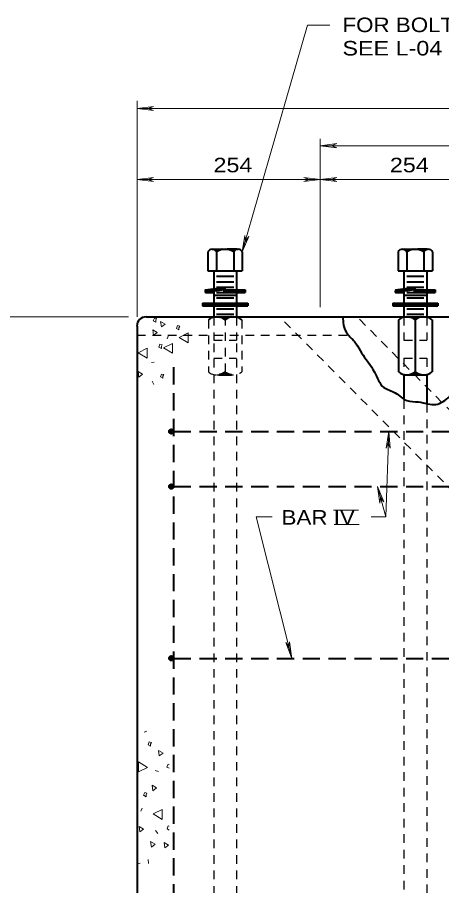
# Model space of a CAD drawing. Extents: x 312583 to 312854, y 144419 to 144597.
# Drawn here: x 312620 to 312642.19, y 144464.5 to 144509.86 of the extents above; entities that cross this region are included whole.
import ezdxf

# ---------------------------------------------------------------- set-up
doc = ezdxf.new("R2010")
doc.units = 0
doc.header["$LTSCALE"] = 0.3
doc.linetypes.add('MEDIUM_DASHED', pattern=[4.5, 3, -1.5])
doc.linetypes.add('SHORT_DASHED', pattern=[2.7, 1.5, -1.2])
doc.layers.add('1', color=7, linetype='Continuous', lineweight=25)
doc.layers.add('2', color=7, linetype='Continuous', lineweight=13)

msp = doc.modelspace()

# ---------------------------------------------------------------- linework, layer by layer
at = {"layer": '1', "lineweight": 40}
for p, q in [((312630.1901, 144497.7458), (312631.5395, 144497.7458)), ((312640.1338, 144497.7458), (312641.4831, 144497.7458)), ((312629.9678, 144497.6001), (312629.9678, 144496.6111)), ((312630.4201, 144497.6001), (312630.4201, 144496.6111)), ((312631.3171, 144497.6001), (312631.3171, 144496.6111)), ((312631.7618, 144497.6001), (312631.7618, 144496.6111)), ((312639.9115, 144497.6001), (312639.9115, 144496.6111)), ((312640.3638, 144497.6001), (312640.3638, 144496.6111)), ((312641.2608, 144497.6001), (312641.2608, 144496.6111)), ((312641.7055, 144497.6001), (312641.7055, 144496.6111)), ((312629.9678, 144496.6111), (312631.7618, 144496.6111)), ((312630.2668, 144496.6111), (312630.2668, 144494.2114)), ((312631.4628, 144496.6111), (312631.4628, 144494.2114)), ((312639.9115, 144496.6111), (312641.7055, 144496.6111)), ((312640.2105, 144496.6111), (312640.2105, 144494.2114)), ((312641.4065, 144496.6111), (312641.4065, 144494.2114)), ((312630.4201, 144496.3274), (312631.3171, 144496.3274)), ((312630.4201, 144496.0438), (312631.3171, 144496.0438)), ((312640.3638, 144496.3274), (312641.2608, 144496.3274)), ((312640.3638, 144496.0438), (312641.2608, 144496.0438)), ((312629.8298, 144495.6221), (312629.8298, 144495.4841)), ((312630.4201, 144495.7678), (312631.3171, 144495.7678)), ((312630.4201, 144495.4841), (312631.3171, 144495.4841)), ((312630.7805, 144495.4841), (312631.9075, 144495.4841)), ((312630.8188, 144495.6221), (312631.9075, 144495.6221)), ((312631.9075, 144495.6221), (312631.9075, 144495.4841)), ((312639.7735, 144495.6221), (312639.7735, 144495.4841)), ((312640.3638, 144495.7678), (312641.2608, 144495.7678)), ((312640.3638, 144495.4841), (312641.2608, 144495.4841)), ((312640.7241, 144495.4841), (312641.8511, 144495.4841)), ((312640.7625, 144495.6221), (312641.8511, 144495.6221)), ((312641.8511, 144495.6221), (312641.8511, 144495.4841)), ((312630.2668, 144495.3384), (312631.4628, 144495.3384)), ((312630.4201, 144495.2004), (312631.3171, 144495.2004)), ((312640.2105, 144495.3384), (312641.4065, 144495.3384)), ((312640.3638, 144495.2004), (312641.2608, 144495.2004)), ((312629.6841, 144494.9168), (312632.0455, 144494.9168)), ((312629.6841, 144494.9168), (312629.6841, 144494.7788)), ((312629.6841, 144494.8784), (312632.0455, 144494.8784)), ((312629.6841, 144494.8401), (312632.0455, 144494.8401)), ((312629.6841, 144494.8094), (312632.0455, 144494.8094)), ((312629.6841, 144494.7788), (312632.0455, 144494.7788)), ((312630.4201, 144494.6331), (312631.3171, 144494.6331)), ((312632.0455, 144494.9168), (312632.0455, 144494.7788)), ((312639.6278, 144494.9168), (312641.9891, 144494.9168)), ((312639.6278, 144494.9168), (312639.6278, 144494.7788)), ((312639.6278, 144494.8784), (312641.9891, 144494.8784)), ((312639.6278, 144494.8401), (312641.9891, 144494.8401)), ((312639.6278, 144494.8094), (312641.9891, 144494.8094)), ((312639.6278, 144494.7788), (312641.9891, 144494.7788)), ((312640.3638, 144494.6331), (312641.2608, 144494.6331)), ((312641.9891, 144494.9168), (312641.9891, 144494.7788)), ((312626.7325, 144494.2114), (312644.9408, 144494.2114)), ((312630.2668, 144494.2114), (312631.4628, 144494.2114)), ((312630.4201, 144494.3494), (312631.3171, 144494.3494)), ((312630.4278, 144494.2114), (312631.3018, 144494.2114)), ((312640.2105, 144494.2114), (312641.4065, 144494.2114)), ((312640.3638, 144494.3494), (312641.2608, 144494.3494)), ((312640.3715, 144494.2114), (312641.2455, 144494.2114)), ((312640.8085, 144494.2114), (312640.8085, 144491.1754)), ((312626.2571, 144493.7284), (312626.2571, 144451.0864)), ((312639.9345, 144494.0504), (312639.9345, 144491.3364)), ((312641.6901, 144494.0504), (312641.6901, 144491.3364)), ((312640.2105, 144491.1984), (312640.2105, 144489.8874)), ((312640.3715, 144491.1754), (312641.2455, 144491.1754)), ((312641.4065, 144491.1984), (312641.4065, 144489.7034))]:
    msp.add_line(p, q, dxfattribs=at)
at = {"layer": '1', "linetype": 'SHORT_DASHED'}
for p, q in [((312630.2668, 144494.2114), (312630.2668, 144493.0001)), ((312630.8648, 144494.2114), (312630.8648, 144491.1754)), ((312631.4628, 144494.2114), (312631.4628, 144493.0001)), ((312646.8421, 144480.9864), (312633.7168, 144494.2114)), ((312646.7655, 144485.1418), (312637.7648, 144494.2114)), ((312640.2105, 144494.2114), (312640.2105, 144493.0001)), ((312641.4065, 144494.2114), (312641.4065, 144493.0001)), ((312629.9908, 144494.0504), (312629.9908, 144491.3364)), ((312631.7465, 144494.0504), (312631.7465, 144491.3364)), ((312626.2571, 144493.2531), (312637.3201, 144493.2531)), ((312630.2668, 144493.0001), (312631.4628, 144493.0001)), ((312630.2668, 144492.8238), (312630.2668, 144459.5811)), ((312631.4628, 144492.8238), (312631.4628, 144459.5811)), ((312640.2105, 144493.0001), (312641.4065, 144493.0001)), ((312630.2668, 144492.0494), (312631.4628, 144492.0494)), ((312640.2105, 144492.0494), (312641.4065, 144492.0494)), ((312640.2105, 144492.0494), (312640.2105, 144491.1984)), ((312641.4065, 144492.0494), (312641.4065, 144491.1984)), ((312630.4278, 144491.1754), (312631.3018, 144491.1754)), ((312640.2105, 144490.6694), (312640.2105, 144459.5811)), ((312641.4065, 144490.4701), (312641.4065, 144459.5811))]:
    msp.add_line(p, q, dxfattribs=at)
at = {"layer": '1', "lineweight": 13}
for p, q in [((312641.3528, 144494.2038), (312641.3451, 144494.1884)), ((312627.9055, 144493.2378), (312627.8288, 144493.0691)), ((312626.2725, 144492.6474), (312626.2725, 144493.1611)), ((312626.2571, 144492.6551), (312626.2725, 144492.6474)), ((312627.0085, 144491.8194), (312627.1618, 144491.8348)), ((312627.0545, 144490.8458), (312627.1388, 144490.6771)), ((312626.2725, 144490.2861), (312626.2571, 144490.2708)), ((312626.6251, 144472.5224), (312626.7708, 144472.5608)), ((312627.2078, 144470.5061), (312627.3765, 144470.4678)), ((312626.5255, 144468.5511), (312626.4488, 144468.3824)), ((312627.2308, 144467.3704), (312627.3381, 144467.2248)), ((312626.2801, 144465.6301), (312626.4258, 144465.6761)), ((312626.8398, 144465.8678), (312626.8628, 144465.6531))]:
    msp.add_line(p, q, dxfattribs=at)
at = {"layer": '1', "linetype": 'MEDIUM_DASHED', "lineweight": 40}
for p, q in [((312628.1738, 144491.5741), (312628.1738, 144451.9068)), ((312628.1738, 144488.2238), (312643.5071, 144488.2238)), ((312628.1738, 144485.3488), (312643.5071, 144485.3488)), ((312628.1738, 144476.3711), (312643.5071, 144476.3711))]:
    msp.add_line(p, q, dxfattribs=at)
at = {"layer": '1', "lineweight": 40}
for points in [[(312630.2515, 144497.7381), (312630.7498, 144497.7381), (312630.6655, 144497.7228), (312630.6118, 144497.7074), (312630.5121, 144497.6768), (312630.4201, 144497.6078), (312630.3895, 144497.6691), (312630.3435, 144497.6998), (312630.2668, 144497.7381), (312630.7115, 144497.7381), (312630.5811, 144497.7074), (312630.4968, 144497.6691), (312630.4278, 144497.6231), (312630.3511, 144497.6921), (312630.2975, 144497.7304), (312630.6578, 144497.7304), (312630.5351, 144497.6921), (312630.4278, 144497.6384), (312630.3281, 144497.7228), (312630.6118, 144497.7304), (312630.4201, 144497.6461), (312630.3435, 144497.7151), (312630.5811, 144497.7228), (312630.4125, 144497.6614), (312630.3588, 144497.7151), (312630.5505, 144497.7151), (312630.4201, 144497.6691), (312630.3818, 144497.7074), (312630.4968, 144497.7074), (312630.4278, 144497.6768), (312630.4048, 144497.6998), (312630.4585, 144497.6998), (312630.4201, 144497.6921)], [(312631.4858, 144497.7381), (312630.9798, 144497.7381), (312631.0641, 144497.7228), (312631.1255, 144497.7074), (312631.2175, 144497.6768), (312631.3095, 144497.6078), (312631.3478, 144497.6691), (312631.3861, 144497.6998), (312631.4628, 144497.7381), (312631.0181, 144497.7381), (312631.1485, 144497.7074), (312631.2405, 144497.6691), (312631.3095, 144497.6231), (312631.3785, 144497.6921), (312631.4321, 144497.7304), (312631.0718, 144497.7304), (312631.1945, 144497.6921), (312631.3095, 144497.6384), (312631.4091, 144497.7228), (312631.1178, 144497.7304), (312631.3095, 144497.6461), (312631.3861, 144497.7151), (312631.1485, 144497.7228), (312631.3171, 144497.6614), (312631.3708, 144497.7151), (312631.1868, 144497.7151), (312631.3095, 144497.6691), (312631.3478, 144497.7074), (312631.2328, 144497.7074), (312631.3018, 144497.6768), (312631.3248, 144497.6998), (312631.2711, 144497.6998), (312631.3095, 144497.6921)], [(312640.1951, 144497.7381), (312640.6935, 144497.7381), (312640.6091, 144497.7228), (312640.5555, 144497.7074), (312640.4558, 144497.6768), (312640.3638, 144497.6078), (312640.3331, 144497.6691), (312640.2871, 144497.6998), (312640.2105, 144497.7381), (312640.6551, 144497.7381), (312640.5248, 144497.7074), (312640.4405, 144497.6691), (312640.3715, 144497.6231), (312640.2948, 144497.6921), (312640.2411, 144497.7304), (312640.6015, 144497.7304), (312640.4788, 144497.6921), (312640.3715, 144497.6384), (312640.2718, 144497.7228), (312640.5555, 144497.7304), (312640.3638, 144497.6461), (312640.2871, 144497.7151), (312640.5248, 144497.7228), (312640.3561, 144497.6614), (312640.3025, 144497.7151), (312640.4941, 144497.7151), (312640.3638, 144497.6691), (312640.3255, 144497.7074), (312640.4405, 144497.7074), (312640.3715, 144497.6768), (312640.3485, 144497.6998), (312640.4021, 144497.6998), (312640.3638, 144497.6921)], [(312641.4295, 144497.7381), (312640.9235, 144497.7381), (312641.0078, 144497.7228), (312641.0691, 144497.7074), (312641.1611, 144497.6768), (312641.2531, 144497.6078), (312641.2915, 144497.6691), (312641.3298, 144497.6998), (312641.4065, 144497.7381), (312640.9618, 144497.7381), (312641.0921, 144497.7074), (312641.1841, 144497.6691), (312641.2531, 144497.6231), (312641.3221, 144497.6921), (312641.3758, 144497.7304), (312641.0155, 144497.7304), (312641.1381, 144497.6921), (312641.2531, 144497.6384), (312641.3528, 144497.7228), (312641.0615, 144497.7304), (312641.2531, 144497.6461), (312641.3298, 144497.7151), (312641.0921, 144497.7228), (312641.2608, 144497.6614), (312641.3145, 144497.7151), (312641.1305, 144497.7151), (312641.2531, 144497.6691), (312641.2915, 144497.7074), (312641.1765, 144497.7074), (312641.2455, 144497.6768), (312641.2685, 144497.6998), (312641.2148, 144497.6998), (312641.2531, 144497.6921)], [(312629.8298, 144495.6221), (312630.8648, 144495.7678), (312630.7805, 144495.4841)], [(312630.2668, 144495.4841), (312629.8298, 144495.4994), (312629.8451, 144495.6144), (312630.8341, 144495.7448), (312630.8035, 144495.6374), (312630.2591, 144495.5608), (312630.2515, 144495.5071), (312629.8528, 144495.5148), (312629.8605, 144495.5914), (312630.8111, 144495.7218), (312630.7881, 144495.6528), (312630.2361, 144495.5608), (312630.2285, 144495.5148), (312629.8681, 144495.5301), (312629.8681, 144495.5684), (312630.7728, 144495.6988), (312630.7728, 144495.6758), (312630.2438, 144495.5761), (312630.2055, 144495.5608), (312630.0981, 144495.5378), (312629.8911, 144495.5454), (312630.7498, 144495.6834), (312630.0291, 144495.5454)], [(312630.8188, 144495.6221), (312629.8298, 144495.4841), (312630.2668, 144495.4841)], [(312630.8035, 144495.4994), (312631.8845, 144495.4994), (312631.8845, 144495.6068), (312630.8418, 144495.5991), (312630.8035, 144495.5148), (312631.8691, 144495.5148), (312631.8615, 144495.5914), (312630.8495, 144495.5838), (312630.8265, 144495.5301), (312631.8461, 144495.5378), (312631.8308, 144495.5684), (312631.8231, 144495.5761), (312630.8571, 144495.5684), (312630.8418, 144495.5454), (312631.8231, 144495.5531)], [(312639.7735, 144495.6221), (312640.8085, 144495.7678), (312640.7241, 144495.4841)], [(312640.2105, 144495.4841), (312639.7735, 144495.4994), (312639.7888, 144495.6144), (312640.7778, 144495.7448), (312640.7471, 144495.6374), (312640.2028, 144495.5608), (312640.1951, 144495.5071), (312639.7965, 144495.5148), (312639.8041, 144495.5914), (312640.7548, 144495.7218), (312640.7318, 144495.6528), (312640.1798, 144495.5608), (312640.1721, 144495.5148), (312639.8118, 144495.5301), (312639.8118, 144495.5684), (312640.7165, 144495.6988), (312640.7165, 144495.6758), (312640.1875, 144495.5761), (312640.1491, 144495.5608), (312640.0418, 144495.5378), (312639.8348, 144495.5454), (312640.6935, 144495.6834), (312639.9728, 144495.5454)], [(312640.7625, 144495.6221), (312639.7735, 144495.4841), (312640.2105, 144495.4841)], [(312640.7471, 144495.4994), (312641.8281, 144495.4994), (312641.8281, 144495.6068), (312640.7855, 144495.5991), (312640.7471, 144495.5148), (312641.8128, 144495.5148), (312641.8051, 144495.5914), (312640.7931, 144495.5838), (312640.7701, 144495.5301), (312641.7898, 144495.5378), (312641.7745, 144495.5684), (312641.7668, 144495.5761), (312640.8008, 144495.5684), (312640.7855, 144495.5454), (312641.7668, 144495.5531)], [(312630.5428, 144494.2038), (312631.1945, 144494.2038), (312631.1178, 144494.1884), (312631.0488, 144494.1731), (312630.9798, 144494.1424), (312630.9338, 144494.1118), (312630.8725, 144494.0734), (312630.8648, 144494.0658), (312630.7421, 144494.1424), (312630.6348, 144494.1808), (312630.5735, 144494.1961), (312631.1485, 144494.2038), (312631.1025, 144494.1961), (312631.0488, 144494.1808), (312630.9798, 144494.1578), (312630.9108, 144494.1194), (312630.8878, 144494.0964), (312630.8648, 144494.0734), (312630.7575, 144494.1501), (312630.6348, 144494.1884), (312631.0641, 144494.1961), (312630.9568, 144494.1578), (312630.8648, 144494.0964), (312630.6808, 144494.1884), (312631.0181, 144494.1884), (312630.8648, 144494.0888), (312630.7191, 144494.1808), (312630.9875, 144494.1808), (312630.8725, 144494.1194), (312630.7728, 144494.1654), (312630.9491, 144494.1731), (312630.8648, 144494.1424), (312630.7651, 144494.1578), (312630.8265, 144494.1271), (312630.8418, 144494.1654), (312630.8571, 144494.1041), (312630.9031, 144494.1501), (312630.9261, 144494.1578), (312630.9568, 144494.1654)], [(312640.4865, 144494.2038), (312641.1381, 144494.2038), (312641.0615, 144494.1884), (312640.9925, 144494.1731), (312640.9235, 144494.1424), (312640.8775, 144494.1118), (312640.8161, 144494.0734), (312640.8085, 144494.0658), (312640.6858, 144494.1424), (312640.5785, 144494.1808), (312640.5171, 144494.1961), (312641.0921, 144494.2038), (312641.0461, 144494.1961), (312640.9925, 144494.1808), (312640.9235, 144494.1578), (312640.8545, 144494.1194), (312640.8315, 144494.0964), (312640.8085, 144494.0734), (312640.7011, 144494.1501), (312640.5785, 144494.1884), (312641.0078, 144494.1961), (312640.9005, 144494.1578), (312640.8085, 144494.0964), (312640.6245, 144494.1884), (312640.9618, 144494.1884), (312640.8085, 144494.0888), (312640.6628, 144494.1808), (312640.9311, 144494.1808), (312640.8161, 144494.1194), (312640.7165, 144494.1654), (312640.8928, 144494.1731), (312640.8085, 144494.1424), (312640.7088, 144494.1578), (312640.7701, 144494.1271), (312640.7855, 144494.1654), (312640.8008, 144494.1041), (312640.8468, 144494.1501), (312640.8698, 144494.1578), (312640.9005, 144494.1654)], [(312630.5428, 144491.1831), (312631.1945, 144491.1831), (312631.1178, 144491.1984), (312631.0488, 144491.2138), (312630.9798, 144491.2444), (312630.9338, 144491.2751), (312630.8725, 144491.3134), (312630.8648, 144491.3211), (312630.7421, 144491.2444), (312630.6348, 144491.1984), (312630.5735, 144491.1908), (312631.1485, 144491.1831), (312631.1025, 144491.1908), (312631.0488, 144491.1984), (312630.9798, 144491.2291), (312630.9108, 144491.2674), (312630.8878, 144491.2904), (312630.8648, 144491.3134), (312630.7575, 144491.2368), (312630.6348, 144491.1908), (312631.0641, 144491.1908), (312630.9568, 144491.2291), (312630.8648, 144491.2904), (312630.6808, 144491.1984), (312631.0181, 144491.1984), (312630.8648, 144491.2981), (312630.7191, 144491.2061), (312630.9875, 144491.1984), (312630.8725, 144491.2674), (312630.7728, 144491.2214), (312630.9491, 144491.2138), (312630.8648, 144491.2368), (312630.7651, 144491.2214), (312630.8265, 144491.2598), (312630.8418, 144491.2214), (312630.8571, 144491.2751), (312630.9031, 144491.2368), (312630.9261, 144491.2291), (312630.9568, 144491.2214)], [(312640.4865, 144491.1831), (312641.1381, 144491.1831), (312641.0615, 144491.1984), (312640.9925, 144491.2138), (312640.9235, 144491.2444), (312640.8775, 144491.2751), (312640.8161, 144491.3134), (312640.8085, 144491.3211), (312640.6858, 144491.2444), (312640.5785, 144491.1984), (312640.5171, 144491.1908), (312641.0921, 144491.1831), (312641.0461, 144491.1908), (312640.9925, 144491.1984), (312640.9235, 144491.2291), (312640.8545, 144491.2674), (312640.8315, 144491.2904), (312640.8085, 144491.3134), (312640.7011, 144491.2368), (312640.5785, 144491.1908), (312641.0078, 144491.1908), (312640.9005, 144491.2291), (312640.8085, 144491.2904), (312640.6245, 144491.1984), (312640.9618, 144491.1984), (312640.8085, 144491.2981), (312640.6628, 144491.2061), (312640.9311, 144491.1984), (312640.8161, 144491.2674), (312640.7165, 144491.2214), (312640.8928, 144491.2138), (312640.8085, 144491.2368), (312640.7088, 144491.2214), (312640.7701, 144491.2598), (312640.7855, 144491.2214), (312640.8008, 144491.2751), (312640.8468, 144491.2368), (312640.8698, 144491.2291), (312640.9005, 144491.2214)]]:
    msp.add_lwpolyline(points, dxfattribs=at)
at = {"layer": '1', "lineweight": 13}
for points in [[(312627.2385, 144494.0351), (312627.2845, 144494.1194), (312627.1695, 144494.1501), (312627.1081, 144493.9968), (312627.2385, 144493.9278)], [(312627.5375, 144493.6901), (312627.7291, 144493.8358), (312627.4915, 144493.9738)], [(312628.4421, 144493.6364), (312628.4958, 144493.7208), (312628.3731, 144493.7514), (312628.3195, 144493.5981), (312628.4421, 144493.5291)], [(312627.1235, 144493.2531), (312627.3151, 144493.3988), (312627.0775, 144493.5368)], [(312628.9328, 144492.8544), (312628.9328, 144493.3758), (312628.4651, 144493.1381)], [(312627.5298, 144492.6704), (312627.5758, 144492.7548), (312627.4531, 144492.7854), (312627.3995, 144492.6321), (312627.5298, 144492.5631)], [(312628.1048, 144492.3101), (312628.1048, 144492.8238), (312627.6371, 144492.5861)], [(312626.7938, 144492.0571), (312626.7938, 144492.5708), (312626.3261, 144492.3331)], [(312626.3491, 144491.0681), (312626.5408, 144491.2138), (312626.3108, 144491.3518)], [(312627.6141, 144491.1064), (312627.6678, 144491.1908), (312627.5451, 144491.2214), (312627.4915, 144491.0758), (312627.6141, 144490.9991)], [(312626.9701, 144471.8861), (312627.0161, 144471.9704), (312626.9011, 144472.0011), (312626.8398, 144471.8478), (312626.9701, 144471.7788)], [(312627.4225, 144471.2804), (312627.6218, 144471.4261), (312627.3841, 144471.5641)], [(312626.3415, 144470.9584), (312626.3415, 144470.4448), (312626.8091, 144470.6748)], [(312627.0851, 144469.4558), (312627.2845, 144469.6014), (312627.0468, 144469.7394)], [(312626.7325, 144469.2488), (312626.7785, 144469.3331), (312626.6635, 144469.3638), (312626.6021, 144469.2181), (312626.7325, 144469.1414)], [(312627.5681, 144467.9608), (312627.5681, 144468.4821), (312627.1005, 144468.2444)], [(312626.4105, 144467.3014), (312626.6021, 144467.4471), (312626.3721, 144467.5928)], [(312627.0085, 144466.5118), (312627.2001, 144466.6574), (312626.9625, 144466.7954)], [(312627.7138, 144466.4658), (312627.9055, 144466.6114), (312627.6755, 144466.7571)]]:
    msp.add_lwpolyline(points, close=True, dxfattribs=at)
for points in [[(312627.9438, 144470.8281), (312627.8825, 144470.8434), (312627.8211, 144470.6901), (312627.9438, 144470.6288)], [(312627.9361, 144467.6004), (312627.8901, 144467.6158), (312627.8288, 144467.4624), (312627.9361, 144467.4011)], [(312626.2571, 144466.4428), (312626.2878, 144466.5041), (312626.2571, 144466.5118)]]:
    msp.add_lwpolyline(points, dxfattribs=at)
at = {"layer": '1', "lineweight": 40}
for centre, radius in [((312628.0502, 144488.2199), 0.1198), ((312628.0502, 144488.2199), 0.0838), ((312628.0502, 144488.2199), 0.0587), ((312628.0502, 144485.3449), 0.1198), ((312628.0502, 144485.3449), 0.0838), ((312628.0502, 144485.3449), 0.0587), ((312628.0502, 144476.374), 0.1198), ((312628.0502, 144476.374), 0.0838), ((312628.0502, 144476.374), 0.0587)]:
    msp.add_circle(centre, radius, dxfattribs=at)
for centre, radius, start, end in [((312630.1914, 144497.4943), 0.2489, 25.60064, 154.39936), ((312630.8648, 144496.9596), 0.7836, 55.04559, 124.95441), ((312631.5382, 144497.4943), 0.2489, 25.60064, 154.39936), ((312640.1351, 144497.4943), 0.2489, 25.60064, 154.39936), ((312640.8085, 144496.9596), 0.7836, 55.04559, 124.95441), ((312641.4819, 144497.4943), 0.2489, 25.60064, 154.39936), ((312630.4266, 144493.5274), 0.6817, 50.00693, 129.99306), ((312631.3029, 144493.5274), 0.6817, 50.00694, 129.99307), ((312640.3702, 144493.5274), 0.6817, 50.00693, 129.99306), ((312641.2465, 144493.5274), 0.6817, 50.00694, 129.99307), ((312640.3702, 144491.8568), 0.6817, 230.00694, 309.99307), ((312641.2465, 144491.8568), 0.6817, 230.00693, 309.99306)]:
    msp.add_arc(centre, radius, start, end, dxfattribs=at)
at = {"layer": '1', "linetype": 'SHORT_DASHED'}
for centre, start, end in [((312630.4266, 144491.8568), 230.00694, 309.99307), ((312631.3029, 144491.8568), 230.00693, 309.99306)]:
    msp.add_arc(centre, 0.6817, start, end, dxfattribs=at)
at = {"layer": '1', "lineweight": 40}
msp.add_spline([(312637.0135, 144494.2114), (312637.1898, 144493.4218), (312637.3431, 144493.2224), (312637.7111, 144492.8084), (312637.9948, 144492.3331), (312638.6695, 144491.3288), (312639.1678, 144490.5238), (312639.7581, 144490.2401), (312640.3638, 144489.8338), (312640.9771, 144489.7648), (312641.8895, 144489.6344), (312642.6025, 144490.0484), (312643.0011, 144490.5238), (312643.0625, 144490.8304)], degree=3, dxfattribs=at)
at = {"layer": '2'}
for p, q in [((312631.7618, 144497.6001), (312635.1735, 144509.4451)), ((312635.1735, 144509.4451), (312636.3465, 144509.4451)), ((312626.2571, 144494.2114), (312626.2571, 144505.4968)), ((312626.2571, 144505.0981), (312627.1235, 144505.2054)), ((312626.2571, 144505.0981), (312669.6198, 144505.0981)), ((312626.2571, 144505.0981), (312627.1235, 144504.9908)), ((312627.1235, 144505.2054), (312626.8475, 144505.0981)), ((312627.1235, 144504.9908), (312626.8475, 144505.0981)), ((312635.8405, 144494.7174), (312635.8405, 144503.5034)), ((312635.8405, 144503.1508), (312636.7068, 144503.2581)), ((312636.7068, 144503.2581), (312636.4308, 144503.1508)), ((312635.8405, 144503.1508), (312655.2448, 144503.1508)), ((312635.8405, 144503.1508), (312636.7068, 144503.0434)), ((312636.7068, 144503.0434), (312636.4308, 144503.1508)), ((312626.2571, 144501.3874), (312627.1235, 144501.4948)), ((312626.2571, 144501.3874), (312627.1235, 144501.2801)), ((312627.1235, 144501.4948), (312626.8475, 144501.3874)), ((312627.1235, 144501.2801), (312626.8475, 144501.3874)), ((312634.9741, 144501.4948), (312635.2501, 144501.3874)), ((312635.8405, 144501.3874), (312634.9741, 144501.4948)), ((312634.9741, 144501.2801), (312635.2501, 144501.3874)), ((312635.8405, 144501.3874), (312634.9741, 144501.2801)), ((312635.8405, 144501.3874), (312636.7068, 144501.4948)), ((312635.8405, 144501.3874), (312636.7068, 144501.2801)), ((312636.7068, 144501.4948), (312636.4308, 144501.3874)), ((312636.7068, 144501.2801), (312636.4308, 144501.3874)), ((312631.7618, 144497.6001), (312631.8998, 144498.4664)), ((312631.7618, 144497.6001), (312632.1068, 144498.4051)), ((312631.8998, 144498.4664), (312631.9228, 144498.1674)), ((312632.1068, 144498.4051), (312631.9228, 144498.1674)), ((312625.8125, 144494.2114), (312618.7438, 144494.2114)), ((312639.2751, 144483.7694), (312639.4208, 144488.2238)), ((312639.4208, 144488.2238), (312639.2828, 144487.3574)), ((312639.4208, 144488.2238), (312639.4975, 144487.3498)), ((312639.2828, 144487.3574), (312639.3978, 144487.6334)), ((312639.4975, 144487.3498), (312639.3978, 144487.6334)), ((312638.8228, 144485.3488), (312638.9608, 144484.4824)), ((312638.8228, 144485.3488), (312639.1678, 144484.5438)), ((312639.2751, 144483.7694), (312638.8228, 144485.3488)), ((312638.9608, 144484.4824), (312638.9838, 144484.7814)), ((312639.1678, 144484.5438), (312638.9838, 144484.7814)), ((312636.5298, 144484.115), (312637.8408, 144484.115)), ((312638.5008, 144483.7694), (312639.2751, 144483.7694)), ((312636.5653, 144483.3544), (312637.8763, 144483.3544)), ((312634.0311, 144477.1914), (312634.1998, 144476.9461)), ((312634.3455, 144476.3711), (312634.0311, 144477.1914)), ((312634.2381, 144477.2374), (312634.1998, 144476.9461)), ((312634.3455, 144476.3711), (312634.2381, 144477.2374))]:
    msp.add_line(p, q, dxfattribs=at)
for points in [[(312626.2571, 144501.3874), (312635.8405, 144501.3874), (312645.4238, 144501.3874)], [(312633.3181, 144483.7694), (312632.4901, 144483.7694), (312634.3455, 144476.3711)]]:
    msp.add_lwpolyline(points, dxfattribs=at)
at = {"layer": '2', "lineweight": 40}
msp.add_arc((312626.7325, 144493.7303), 0.4792, 90, 180, dxfattribs=at)

# ---------------------------------------------------------------- texts
at = {"layer": '2'}
for s, width, p in [('FOR BOLT DETAIL', 1.15, (312636.9981, 144509.0838)), ('SEE L-04', 1.2, (312636.9981, 144507.8638)), ('254 ', 1.2, (312630.2563, 144501.7612)), ('254 ', 1.2, (312639.4779, 144501.7612)), ('BAR IV', 1.15, (312633.8149, 144483.3559))]:
    msp.add_text(s, height=0.76, dxfattribs=dict(at, width=width)).set_placement(p)

doc.saveas('drawing.dxf')
